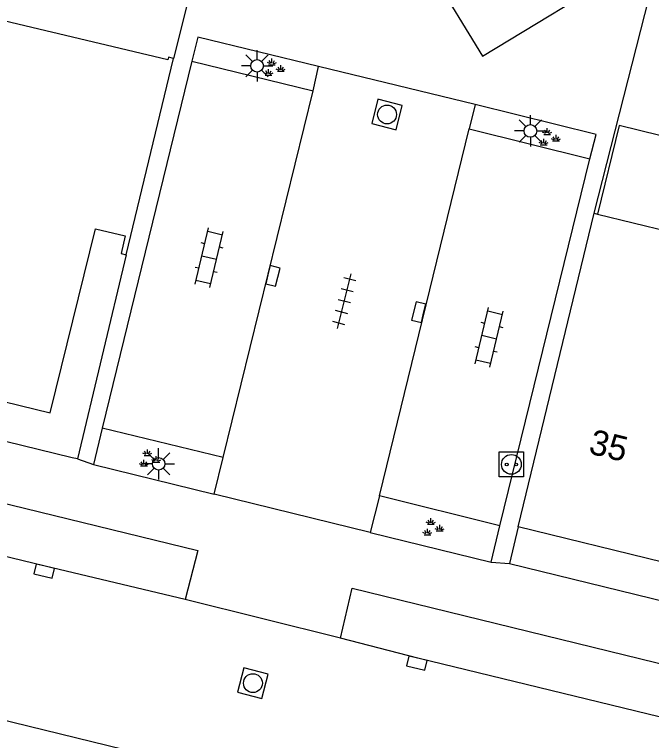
# Model space of a CAD drawing. Extents: x 125000 to 129004, y 397500 to 399008.
# Drawn here: x 126516.3 to 126541.62, y 397923.5 to 397952.37 of the extents above; entities that cross this region are included whole.
import ezdxf

# ---------------------------------------------------------------- set-up
doc = ezdxf.new("R2010")
doc.units = 0
for name, color, linetype in [('gg-afsc-hekwerk', 7, 'Continuous'), ('gg-afsc-muur', 7, 'Continuous'), ('gg-anno-huisnummerreeks BGT', 7, 'Continuous'), ('gg-bbg-hoofdgebouw', 7, 'Continuous'), ('gg-bbg-luifel en loopbrug', 7, 'Continuous'), ('gg-knt-verharding', 7, 'Continuous'), ('gg-knt-verharding nz', 7, 'Continuous'), ('gt-grn-weggrens', 7, 'Continuous'), ('gt-symb-groenvak', 7, 'Continuous'), ('gt-symb-klinker verharding', 7, 'Continuous'), ('gt-symb-kolk', 7, 'Continuous'), ('gt-symb-laadpunt elektrisch vervoer', 7, 'Continuous'), ('gt-symb-lichtmast', 7, 'Continuous'), ('gt-symb-rioolschacht', 7, 'Continuous'), ('gt-symb-tegel verharding', 7, 'Continuous')]:
    doc.layers.add(name, color=color, linetype=linetype)

# ---------------------------------------------------------------- blocks, each defined once
blk = doc.blocks.new('gt0-LEV')
at = {"layer": 'gt-symb-laadpunt elektrisch vervoer'}
blk.add_lwpolyline([(-0.486, 0.501), (0.486, 0.501), (0.486, -0.499), (-0.486, -0.499)], close=True, dxfattribs=at)
for centre, radius in [((0, 0), 0.393), ((-0.186, 0), 0.0566), ((0.186, 0), 0.0566)]:
    blk.add_circle(centre, radius, dxfattribs=at)
blk = doc.blocks.new('gt0-GRVAK')
at = {"layer": 'gt-symb-groenvak'}
for p, q in [((-0.091, 0.211), (-0.156, 0.322)), ((-0.047, 0.214), (-0.047, 0.393)), ((-0.004, 0.211), (0.061, 0.322)), ((-0.11, 0.189), (-0.228, 0.24)), ((-0.182, 0.153), (0.088, 0.153)), ((0.015, 0.189), (0.133, 0.24)), ((0.262, -0.052), (0.197, 0.059)), ((0.305, -0.049), (0.305, 0.13)), ((0.349, -0.052), (0.414, 0.059)), ((-0.245, -0.228), (-0.363, -0.177)), ((-0.318, -0.264), (-0.047, -0.264)), ((-0.226, -0.206), (-0.291, -0.095)), ((-0.183, -0.203), (-0.183, -0.024)), ((-0.139, -0.206), (-0.074, -0.095)), ((-0.12, -0.228), (-0.002, -0.177)), ((0.243, -0.074), (0.125, -0.023)), ((0.17, -0.11), (0.441, -0.11)), ((0.368, -0.074), (0.486, -0.023))]:
    blk.add_line(p, q, dxfattribs=at)
blk = doc.blocks.new('gt0-KL1')
at = {"layer": 'gt-symb-klinker verharding'}
for p, q in [((-1.15, 0.3), (1.15, 0.3)), ((-1, -0.3), (-1, 0.3)), ((-0.5, 0.3), (-0.5, 0.45)), ((0, -0.3), (0, 0.3)), ((0.5, 0.3), (0.5, 0.45)), ((1, -0.3), (1, 0.3)), ((-1.15, -0.3), (1.15, -0.3)), ((-0.5, -0.45), (-0.5, -0.3)), ((0.5, -0.45), (0.5, -0.3))]:
    blk.add_line(p, q, dxfattribs=at)
blk = doc.blocks.new('gt0-LMAST')
at = {"layer": 'gt-symb-lichtmast'}
for p, q in [((-0.005, 0.246), (-0.005, 0.621)), ((-0.182, 0.173), (-0.447, 0.438)), ((0.172, 0.173), (0.437, 0.438)), ((-0.255, -0.004), (-0.63, -0.004)), ((-0.182, -0.181), (-0.447, -0.446)), ((-0.005, -0.254), (-0.005, -0.629)), ((0.437, -0.446), (0.172, -0.181)), ((0.245, -0.004), (0.62, -0.004))]:
    blk.add_line(p, q, dxfattribs=at)
blk.add_circle((-0.005, -0.004), 0.25, dxfattribs=at)
blk = doc.blocks.new('gt0-KOLK')
at = {"layer": 'gt-symb-kolk'}
blk.add_lwpolyline([(0, 0), (0.375, 0), (0.375, 0.4), (-0.375, 0.4), (-0.375, 0), (0, 0)], dxfattribs=at)
blk = doc.blocks.new('gt0-TEG1')
at = {"layer": 'gt-symb-tegel verharding'}
for p, q in [((-1.125, 0), (1.125, 0)), ((-0.9, -0.25), (-0.9, 0.25)), ((-0.45, -0.25), (-0.45, 0.25)), ((0, -0.25), (0, 0.25)), ((0.45, -0.25), (0.45, 0.25)), ((0.9, -0.25), (0.9, 0.25))]:
    blk.add_line(p, q, dxfattribs=at)
blk = doc.blocks.new('gt0-RS')
at = {"layer": 'gt-symb-rioolschacht'}
blk.add_lwpolyline([(-0.5, -0.5), (0.5, -0.5), (0.5, 0.5), (-0.5, 0.5)], close=True, dxfattribs=at)
blk.add_circle((0, 0), 0.375, dxfattribs=at)

msp = doc.modelspace()

# ---------------------------------------------------------------- linework, layer by layer
at = {"layer": 'gg-afsc-hekwerk'}
for p, q in [((126525.236, 397961.145), (126522.62, 397950.61)), ((126539.333, 397944.462), (126542.033, 397955.029))]:
    msp.add_line(p, q, dxfattribs=at)
at = {"layer": 'gg-afsc-muur'}
for p, q in [((126520.738, 397942.814), (126518.797, 397934.695)), ((126518.797, 397934.695), (126518.593, 397934.743))]:
    msp.add_line(p, q, dxfattribs=at)
at = {"layer": 'gg-bbg-hoofdgebouw'}
for p, q in [((126520.738, 397942.814), (126522.62, 397950.61)), ((126536.317, 397931.997), (126539.333, 397944.462)), ((126539.333, 397944.462), (126539.464, 397944.43)), ((126539.464, 397944.43), (126545.08, 397943.054)), ((126542.051, 397930.591), (126536.317, 397931.997))]:
    msp.add_line(p, q, dxfattribs=at)
for points in [[(126522.62, 397950.61), (126522.416, 397950.666), (126522.387, 397950.56), (126515.076, 397952.302)], [(126511.577, 397938.031), (126517.717, 397936.525), (126519.517, 397943.849), (126520.703, 397943.563), (126520.534, 397942.863), (126520.738, 397942.814)]]:
    msp.add_lwpolyline(points, dxfattribs=at)
at = {"layer": 'gg-bbg-luifel en loopbrug'}
msp.add_lwpolyline([(126545.08, 397943.054), (126545.941, 397946.57), (126540.326, 397947.948), (126539.464, 397944.43)], dxfattribs=at)
at = {"layer": 'gg-knt-verharding'}
for p, q in [((126523.352, 397950.514), (126519.783, 397935.916)), ((126523.352, 397950.514), (126528.164, 397949.326)), ((126528.164, 397949.326), (126528.385, 397950.294)), ((126524.597, 397934.751), (126528.164, 397949.326)), ((126534.603, 397948.781), (126534.372, 397947.815)), ((126530.805, 397933.227), (126534.372, 397947.815)), ((126534.372, 397947.815), (126539.171, 397946.631)), ((126535.595, 397932.034), (126539.171, 397946.631)), ((126519.783, 397935.916), (126519.435, 397934.471)), ((126524.597, 397934.751), (126519.783, 397935.916)), ((126519.435, 397934.471), (126524.235, 397933.297)), ((126524.235, 397933.297), (126524.597, 397934.751)), ((126530.805, 397933.227), (126530.44, 397931.771)), ((126535.595, 397932.034), (126530.805, 397933.227)), ((126535.242, 397930.595), (126535.595, 397932.034)), ((126536.317, 397931.997), (126535.979, 397930.532)), ((126530.44, 397931.771), (126535.242, 397930.595)), ((126529.258, 397927.574), (126523.08, 397929.101))]:
    msp.add_line(p, q, dxfattribs=at)
for points in [[(126518.593, 397934.743), (126428.617, 397956.791), (126418.654, 397959.22)], [(126532.877, 397954.039), (126534.894, 397950.708), (126540.762, 397954.279), (126538.744, 397957.611), (126532.877, 397954.039)], [(126528.385, 397950.294), (126523.588, 397951.459), (126523.352, 397950.514)], [(126539.171, 397946.631), (126539.415, 397947.595), (126534.603, 397948.781)], [(126471.076, 397941.783), (126471.551, 397943.765), (126523.586, 397931.05), (126523.08, 397929.101)], [(126653.577, 397890.595), (126642.67, 397893.286), (126528.84, 397921.128), (126461.283, 397937.669)], [(126535.979, 397930.532), (126659.361, 397900.329), (126665.374, 397898.886)], [(126529.258, 397927.574), (126529.715, 397929.557), (126608.024, 397910.375), (126607.541, 397908.385)]]:
    msp.add_lwpolyline(points, dxfattribs=at)
at = {"layer": 'gg-knt-verharding nz'}
for points in [[(126523.08, 397929.101), (126517.524, 397930.428), (126501.556, 397934.302), (126486.82, 397937.891), (126471.668, 397941.621), (126471.076, 397941.783)], [(126607.541, 397908.385), (126595.597, 397911.185), (126579.956, 397915.125), (126564.162, 397918.959), (126547.703, 397923.035), (126532.333, 397926.769), (126529.258, 397927.574)]]:
    msp.add_lwpolyline(points, dxfattribs=at)
at = {"layer": 'gt-grn-weggrens'}
for p, q in [((126534.603, 397948.781), (126528.385, 397950.294)), ((126518.797, 397934.695), (126519.435, 397934.471)), ((126530.44, 397931.771), (126524.235, 397933.297)), ((126535.242, 397930.595), (126535.979, 397930.532))]:
    msp.add_line(p, q, dxfattribs=at)

# ---------------------------------------------------------------- block references
at = {"layer": 'gt-symb-groenvak'}
for p in [(126526.577, 397950.217), (126537.516, 397947.448), (126521.628, 397934.68), (126532.893, 397931.944)]:
    msp.add_blockref('gt0-GRVAK', p, dxfattribs=at)
at = {"layer": 'gt-symb-klinker verharding'}
for p, rotation in [((126524.037, 397942.693), 76.46414363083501), ((126535.163, 397939.526), 76.46414363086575)]:
    msp.add_blockref('gt0-KL1', p, dxfattribs=dict(at, rotation=rotation))
at = {"layer": 'gt-symb-kolk'}
for p, rotation in [((126526.374, 397942.017), -103.77214543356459), ((126532.56, 397940.484), 76.1165819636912), ((126517.524, 397930.428), 166.5889281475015), ((126532.333, 397926.769), 166.352761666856)]:
    msp.add_blockref('gt0-KOLK', p, dxfattribs=dict(at, rotation=rotation))
at = {"layer": 'gt-symb-laadpunt elektrisch vervoer'}
msp.add_blockref('gt0-LEV', (126536.049, 397934.476), dxfattribs=at)
at = {"layer": 'gt-symb-lichtmast'}
for p in [(126525.946, 397950.33), (126536.808, 397947.741), (126522.033, 397934.504)]:
    msp.add_blockref('gt0-LMAST', p, dxfattribs=at)
at = {"layer": 'gt-symb-rioolschacht'}
for p, rotation in [((126531.105, 397948.392), -104.3002774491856), ((126525.775, 397925.78), 165.40804379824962)]:
    msp.add_blockref('gt0-RS', p, dxfattribs=dict(at, rotation=rotation))
at = {"layer": 'gt-symb-tegel verharding', "rotation": 75.93596328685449}
msp.add_blockref('gt0-TEG1', (126529.409, 397940.966), dxfattribs=at)

# ---------------------------------------------------------------- texts
at = {"layer": 'gg-anno-huisnummerreeks BGT'}
msp.add_text('35', height=1, rotation=346.2, dxfattribs=at).set_placement((126539.077, 397934.923))

doc.saveas('drawing.dxf')
